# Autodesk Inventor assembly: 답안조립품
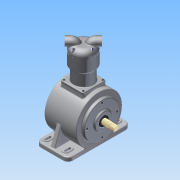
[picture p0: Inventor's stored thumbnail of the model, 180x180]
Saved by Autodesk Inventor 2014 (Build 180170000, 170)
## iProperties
Created: 2015-06
Part Number: 답안조립품
Document SubType Name: Assembly
Designer: Administrator
Author: Administrator
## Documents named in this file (15)
- C:\Users\Administrator\Desktop\450605V1033\답안조립품.iam
- C:\Users\Administrator\Desktop\450605V1033\1-본체.ipt
- C:\Users\Administrator\Desktop\450605V1033\베어링 6204.ipt
- C:\Users\Administrator\Desktop\450605V1033\메인커버.ipt
- C:\Users\Administrator\Desktop\450605V1033\오일실.ipt
- C:\Users\Administrator\Desktop\450605V1033\메인 크랭크 축-구동부.ipt
- C:\Users\Administrator\Desktop\450605V1033\크랭크 서브축.ipt
- C:\Users\Administrator\Desktop\450605V1033\베어링 NA 4902.ipt
- C:\Users\Administrator\Desktop\450605V1033\커넥팅 로드.ipt
- C:\Users\Administrator\Desktop\450605V1033\실린더.ipt
- C:\Users\Administrator\Desktop\450605V1033\실린더헤드.ipt
- C:\Users\Administrator\Desktop\450605V1033\피스톤 핀.ipt
- C:\Users\Administrator\Desktop\450605V1033\피스톤.ipt
- C:\Users\Administrator\Desktop\450605V1033\M5x0.8.ipt
- C:\Users\Administrator\Desktop\450605V1033\M4x0.7.ipt
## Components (15 placed, 5 different names)
1. 1-본체:1
2. 피스톤 핀:1
3. 피스톤:1
4. M4x0.7:1
5. M4x0.7:2
6. M4x0.7:3
7. M4x0.7:5
8. M5x0.8:1
9. M5x0.8:2
10. M5x0.8:3
11. M5x0.8:4
12. M4x0.7:4
13. M4x0.7:6
14. M4x0.7:7
15. M4x0.7:8
